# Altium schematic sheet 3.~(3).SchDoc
size 420 x 297 mm
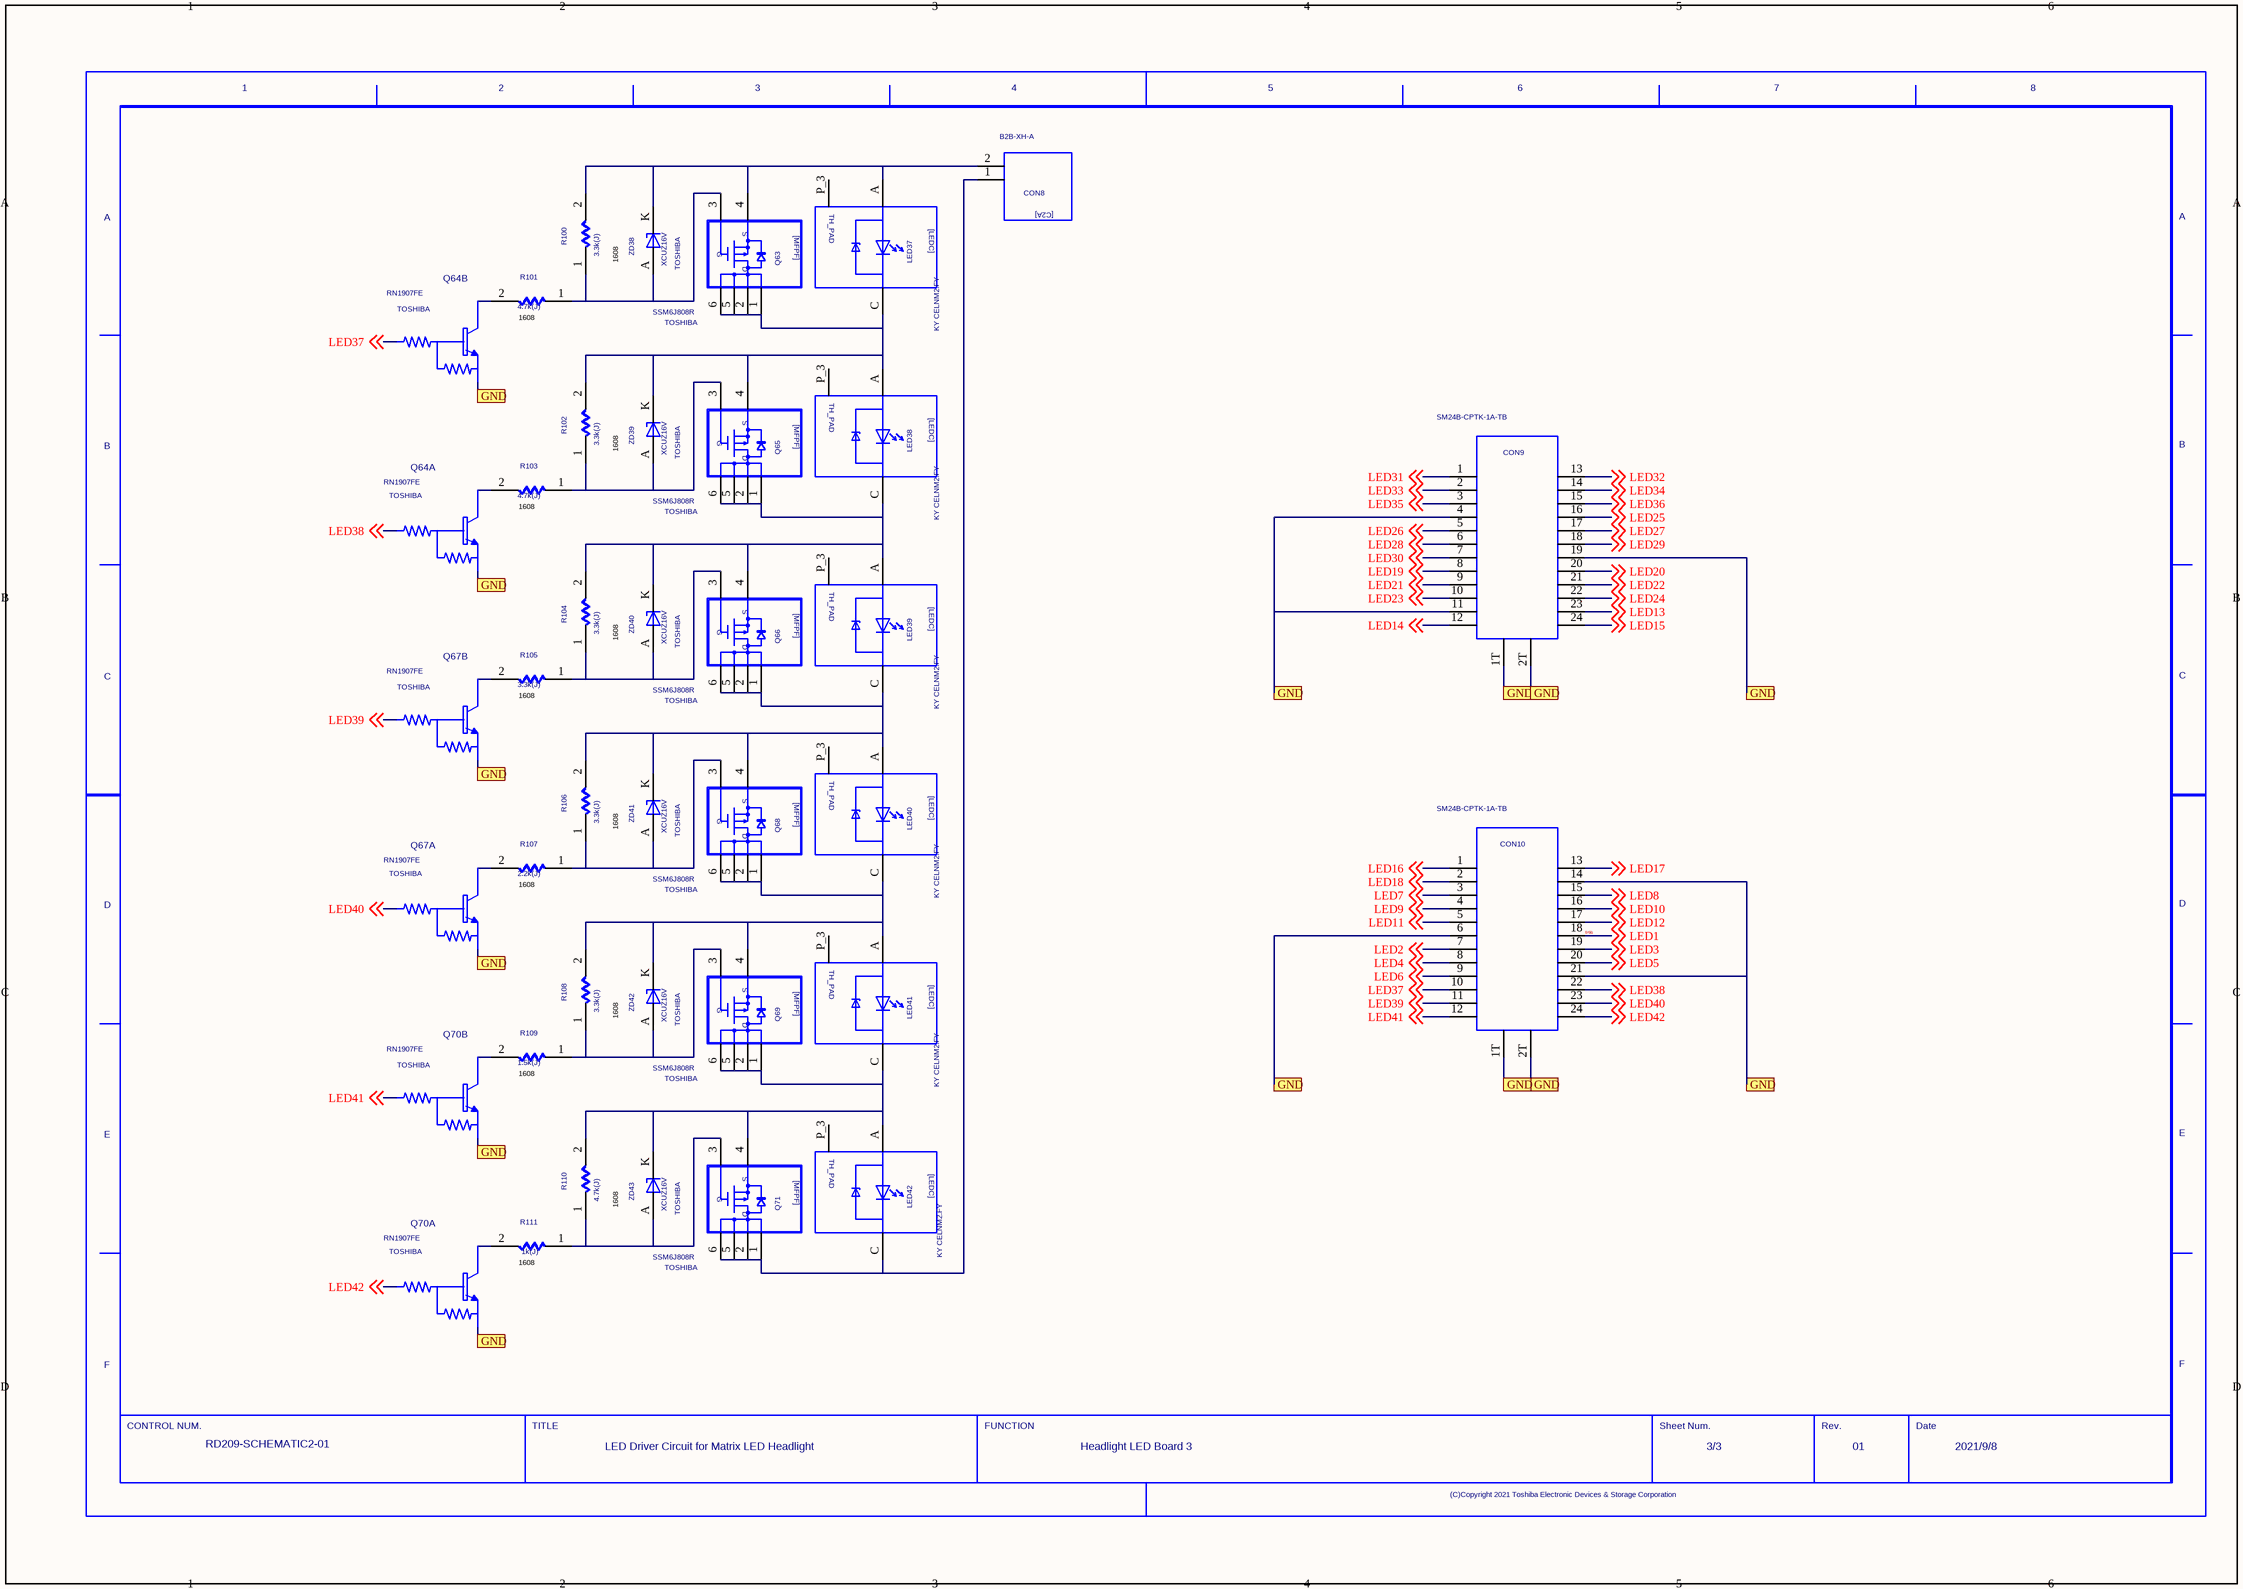
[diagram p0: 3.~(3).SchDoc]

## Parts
CON8  VAL3: B2B-XH-A  (hidden comment: C2A)
CON9  VAL3: SM24B-CPTK-1A-TB  (hidden comment: SM24B_CPTK_1A_TB)
CON10  VAL3: SM24B-CPTK-1A-TB  (hidden comment: SM24B_CPTK_1A_TB)
LED37  VAL3: KY CELNM2.FY  (hidden comment: LEDC)
LED38  VAL3: KY CELNM2.FY  (hidden comment: LEDC)
LED39  VAL3: KY CELNM2.FY  (hidden comment: LEDC)
LED40  VAL3: KY CELNM2.FY  (hidden comment: LEDC)
LED41  VAL3: KY CELNM2.FY  (hidden comment: LEDC)
LED42  VAL3: KY CELNM2.FY  (hidden comment: LEDC)
Q63  USERCOMPTEXT3: TOSHIBA  VAL3: SSM6J808R  (hidden comment: MFPF)
Q64  USERCOMPTEXT3: TOSHIBA  VAL3: RN1907FE  (hidden comment: RN1907FE_1)  (parts A,B of 2)
Q65  USERCOMPTEXT3: TOSHIBA  VAL3: SSM6J808R  (hidden comment: MFPF)
Q66  USERCOMPTEXT3: TOSHIBA  VAL3: SSM6J808R  (hidden comment: MFPF)
Q67  USERCOMPTEXT3: TOSHIBA  VAL3: RN1907FE  (hidden comment: RN1907FE_1)  (parts A,B of 2)
Q68  USERCOMPTEXT3: TOSHIBA  VAL3: SSM6J808R  (hidden comment: MFPF)
Q69  USERCOMPTEXT3: TOSHIBA  VAL3: SSM6J808R  (hidden comment: MFPF)
Q70  USERCOMPTEXT3: TOSHIBA  VAL3: RN1907FE  (hidden comment: RN1907FE_1)  (parts A,B of 2)
Q71  USERCOMPTEXT3: TOSHIBA  VAL3: SSM6J808R  (hidden comment: MFPF)
R100  VAL1: 3.3k(J)  (hidden comment: R)
R101  VAL1: 4.7k(J)  (hidden comment: R)
R102  VAL1: 3.3k(J)  (hidden comment: R)
R103  VAL1: 4.7k(J)  (hidden comment: R)
R104  VAL1: 3.3k(J)  (hidden comment: R)
R105  VAL1: 3.3k(J)  (hidden comment: R)
R106  VAL1: 3.3k(J)  (hidden comment: R)
R107  VAL1: 2.2k(J)  (hidden comment: R)
R108  VAL1: 3.3k(J)  (hidden comment: R)
R109  VAL1: 1.5k(J)  (hidden comment: R)
R110  VAL1: 4.7k(J)  (hidden comment: R)
R111  VAL1: 1k(J)  (hidden comment: R)
U?  DATE: 2021/9/8  REVISION: 01  SHEETNUMBER: 3/3  FUNCTION: Headlight LED Board 3  TITLE: LED Driver Circuit for / Matrix LED Headlight  DRAWINGNUMBER: RD209-SCHEMATIC2-01  (hidden comment: WAKU_DEF100)
ZD38  USERCOMPTEXT3: TOSHIBA  VAL3: XCUZ16V  (hidden comment: ZD)
ZD39  USERCOMPTEXT3: TOSHIBA  VAL3: XCUZ16V  (hidden comment: ZD)
ZD40  USERCOMPTEXT3: TOSHIBA  VAL3: XCUZ16V  (hidden comment: ZD)
ZD41  USERCOMPTEXT3: TOSHIBA  VAL3: XCUZ16V  (hidden comment: ZD)
ZD42  USERCOMPTEXT3: TOSHIBA  VAL3: XCUZ16V  (hidden comment: ZD)
ZD43  USERCOMPTEXT3: TOSHIBA  VAL3: XCUZ16V  (hidden comment: ZD)

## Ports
GND

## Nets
LED2: CON10.7 ; off-sheet LED2
LED3: CON10.19 ; off-sheet LED3
LED4: CON10.8 ; off-sheet LED4
LED5: CON10.20 ; off-sheet LED5
LED6: CON10.9 ; off-sheet LED6
LED7: CON10.3 ; off-sheet LED7
LED8: CON10.15 ; off-sheet LED8
LED9: CON10.4 ; off-sheet LED9
LED10: CON10.16 ; off-sheet LED10
LED11: CON10.5 ; off-sheet LED11
LED12: CON10.17 ; off-sheet LED12
LED13: CON9.23 ; off-sheet LED13
LED14: CON9.12 ; off-sheet LED14
LED15: CON9.24 ; off-sheet LED15
LED16: CON10.1 ; off-sheet LED16
LED17: CON10.13 ; off-sheet LED17
LED18: CON10.2 ; off-sheet LED18
LED19: CON9.8 ; off-sheet LED19
LED20: CON9.20 ; off-sheet LED20
LED21: CON9.9 ; off-sheet LED21
LED22: CON9.21 ; off-sheet LED22
LED23: CON9.10 ; off-sheet LED23
LED24: CON9.22 ; off-sheet LED24
LED25: CON9.16 ; off-sheet LED25
LED26: CON9.5 ; off-sheet LED26
LED27: CON9.17 ; off-sheet LED27
LED28: CON9.6 ; off-sheet LED28
LED29: CON9.18 ; off-sheet LED29
LED30: CON9.7 ; off-sheet LED30
LED31: CON9.1 ; off-sheet LED31
LED32: CON9.13 ; off-sheet LED32
LED33: CON9.2 ; off-sheet LED33
LED34: CON9.14 ; off-sheet LED34
LED35: CON9.3 ; off-sheet LED35
LED36: CON9.15 ; off-sheet LED36
LED37: CON10.10 Q64.5 ; off-sheet LED37
LED38: CON10.22 Q64.2 ; off-sheet LED38
LED39: CON10.11 Q67.5 ; off-sheet LED39
LED40: CON10.23 Q67.2 ; off-sheet LED40
LED41: CON10.12 Q70.5 ; off-sheet LED41
LED42: CON10.24 Q70.2 ; off-sheet LED42
LED+7: CON8.2 LED37.A Q63.4 R100.2 ZD38.K(C)
SIG1: CON10.18 ; off-sheet LED1  [also labelled LED1]
SIG172: Q68.3 R106.1 R107.1 ZD41.A
SIG174: CON9.1T CON9.2T CON9.4 CON9.11 CON9.19 CON10.1T CON10.2T CON10.6 CON10.14 CON10.21 Q64.1 Q64.4 Q67.1 Q67.4 Q70.1 Q70.4 ; port GND  [also labelled SIG179, SIG182, SIG189, SIG195, SIG202, SIG203, SIG204, SIG205, SIG209, SIG210, SIG212, SIG213]
SIG175: LED40.C LED41.A Q68.1 Q68.2 Q68.5 Q68.6 Q69.4 R108.2 ZD42.K(C)
SIG176: Q65.3 R102.1 R103.1 ZD39.A
SIG177: Q67.6 R107.2
SIG180: Q67.3 R105.2
SIG181: Q70.6 R111.2
SIG183: Q70.3 R109.2
SIG187: Q71.3 R110.1 R111.1 ZD43.A
SIG191: LED37.C LED38.A Q63.1 Q63.2 Q63.5 Q63.6 Q65.4 R102.2 ZD39.K(C)
SIG192: LED38.C LED39.A Q65.1 Q65.2 Q65.5 Q65.6 Q66.4 R104.2 ZD40.K(C)
SIG194: LED41.C LED42.A Q69.1 Q69.2 Q69.5 Q69.6 Q71.4 R110.2 ZD43.K(C)
SIG197: Q64.3 R101.2
SIG198: Q63.3 R100.1 R101.1 ZD38.A
SIG199: Q64.6 R103.2
SIG229: Q66.3 R104.1 R105.1 ZD40.A
SIG230: LED39.C LED40.A Q66.1 Q66.2 Q66.5 Q66.6 Q68.4 R106.2 ZD41.K(C)
SIG231: Q69.3 R108.1 R109.1 ZD42.A
SIG232: CON8.1 LED42.C Q71.1 Q71.2 Q71.5 Q71.6

Not connected (* = marked no-connect by the designer): LED37 P_3(NC); LED38 P_3(NC); LED39 P_3(NC); LED40 P_3(NC); LED41 P_3(NC); LED42 P_3(NC)

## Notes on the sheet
- 1608
- (near R101) 1608
- (near R103) 1608
- (near R105) 1608
- (near R107) 1608
- (near R109) 1608
- (near R111) 1608

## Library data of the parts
CON8 = C2A: SAVEAREA0: -4611,-206,24632,18258; SAVECOUNT: 25; TIME: 13:28:28; UPDATEUSER: tomizawa-y; UPDATETIME: 12:08:31; OriginalSymbolOrigin: (2540,15240)
CON9 CON10 = SM24B_CPTK_1A_TB: TIME: 12:18:04; UPDATEUSER: t5459927; UPDATETIME: 10:12:38; SAVECOUNT: 3; SAVEAREA0: -83685,-38329,109566,68648; OriginalSymbolOrigin: (5080,43180); COMPONENTNAME: GAS220000030
LED37-LED42 = LEDC: SAVEAREA0: -10936,-329,35896,28705; TIME: 14:49:55; UPDATEUSER: fukuda-y; UPDATETIME: 15:53:51; SAVECOUNT: 15; OriginalSymbolOrigin: (5080,25400); COMPONENTNAME: LED; CDBNAME: KW
Q63 Q65 Q66 Q68 Q69 Q71 = MFPF: SAVECOUNT: 11; SAVEAREA0: -6011,0,28984,22860; OriginalSymbolOrigin: (5080,20320); COMPONENTNAME: TSOP6F
Q64 Q67 Q70 = RN1907FE_1: COMP: ES6; TIME: 08:46:53; UPDATEUSER: t5459927; UPDATETIME: 14:30:50; SAVECOUNT: 6; SAVEAREA0: -3836,-13019,18528,3377; OriginalSymbolOrigin: (0,5080); CaptureCellPackProp: RN1907FE_1A
R100 R109 = R: OriginalSymbolOrigin: (5080,5080); COMPONENTNAME: R0603_1; VAL2: 100mW
R101 R108 = R: OriginalSymbolOrigin: (5080,5080); COMPONENTNAME: R0603_2; VAL2: 100mW
R102 = R: OriginalSymbolOrigin: (5080,5080); VAL2: 100mW; COMPONENTNAME: R0603_3
R103 R105 = R: OriginalSymbolOrigin: (5080,5080); COMPONENTNAME: R0603_4; VAL2: 100mW
R104 R107 = R: OriginalSymbolOrigin: (5080,5080); COMPONENTNAME: R0603_5; VAL2: 100mW
R106 = R: OriginalSymbolOrigin: (5080,5080); VAL2: 100mW; COMPONENTNAME: R0603_6
R110 = R: OriginalSymbolOrigin: (5080,5080); VAL2: 100mW; COMPONENTNAME: R0603_7
R111 = R: OriginalSymbolOrigin: (5080,5080); COMPONENTNAME: R0603_8; VAL2: 100mW
U? = WAKU_DEF100: PLOTTIME: HH:MM; SAVEAREA0: 148187,-66180,486823,89919; TIME: 14:30:25; UPDATEUSER: t5459927; UPDATETIME: 14:28:23; SAVECOUNT: 6; OriginalSymbolOrigin: (10160,284480)
ZD38-ZD43 = ZD: SAVEAREA0: -4630,-153,17114,13055; TIME: 14:49:55; UPDATEUSER: fukuda-y; UPDATETIME: 08:18:42; SAVECOUNT: 6; OriginalSymbolOrigin: (5080,5080); COMPONENTNAME: USC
